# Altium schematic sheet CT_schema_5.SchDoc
size 242 x 245 mm
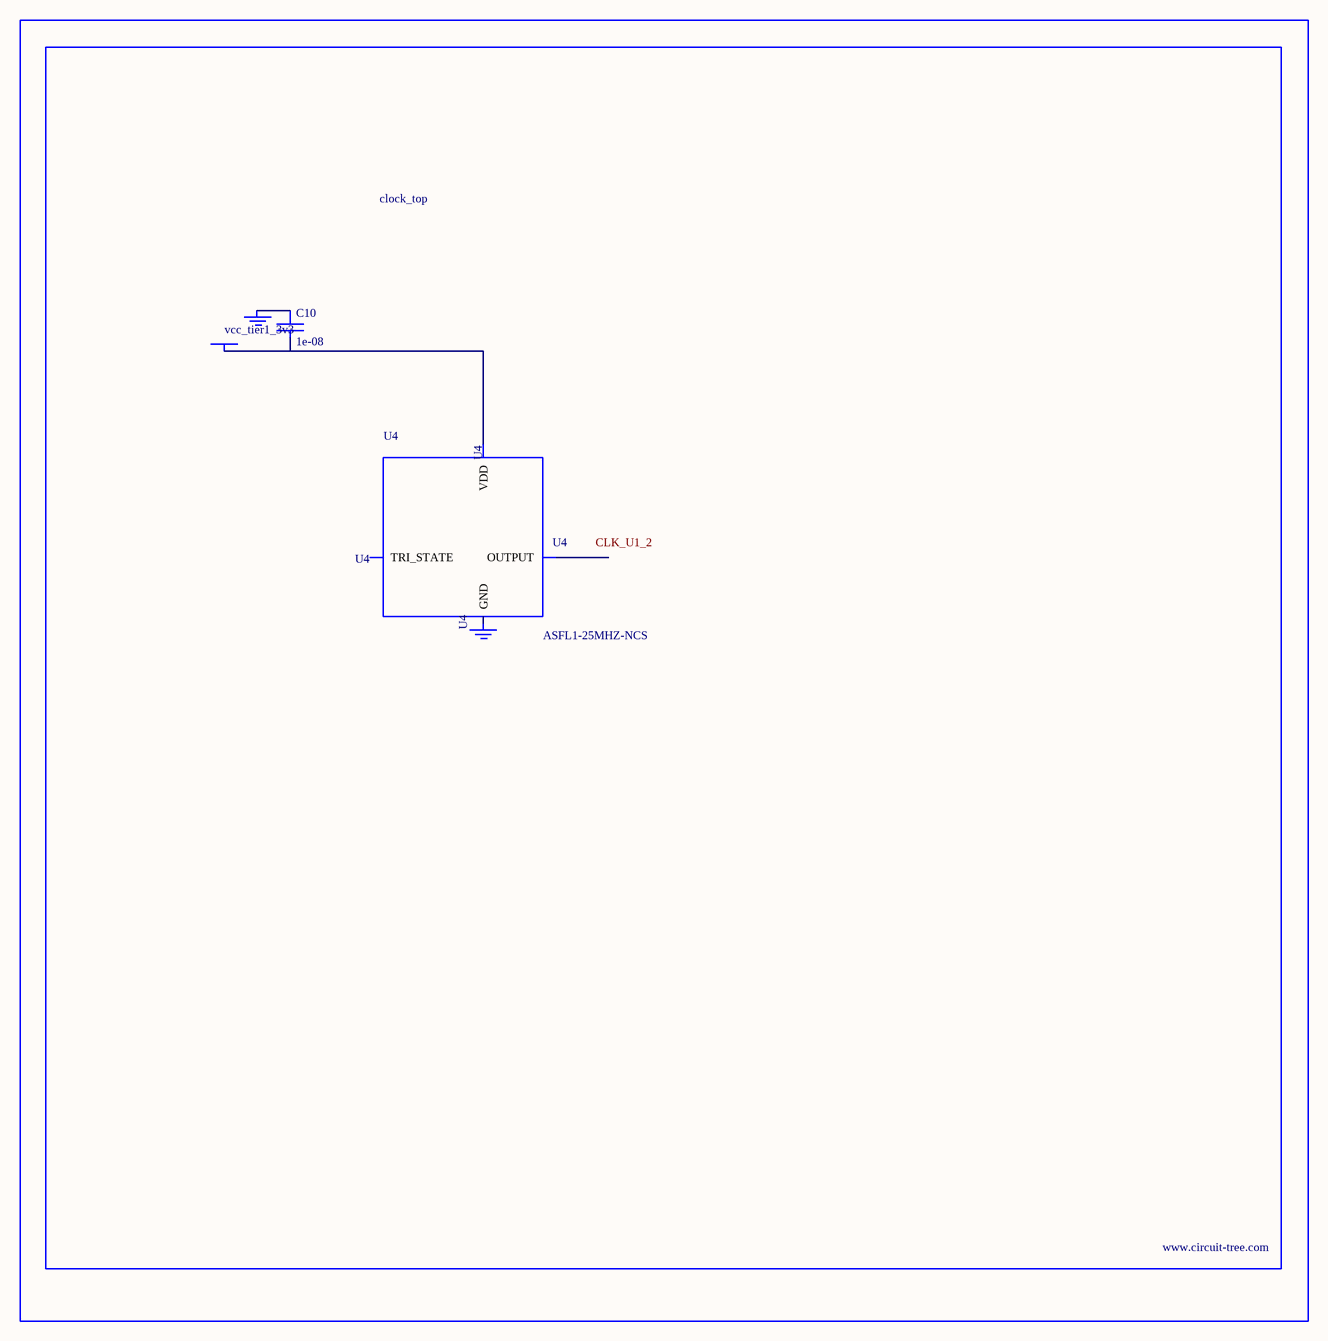
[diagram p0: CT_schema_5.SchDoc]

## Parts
BORDER4  (no value)
C10  1e-08  [C0402]
GND_INSTANCE_4_0  (no value)
GND_INSTANCE_4_1  (no value)
POWER_INSTANCE_4_0  vcc_tier1_3v3
U4  ASFL1-25MHZ-NCS  [ASFL1]

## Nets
NetC10_1: C10.1 GND_INSTANCE_4_0.0(GND)
NetC10_2: C10.2 POWER_INSTANCE_4_0.0(PWR) U4.4(VDD)

Not connected (* = marked no-connect by the designer): GND_INSTANCE_4_1 0(GND); U4 1(TRI_STATE) 2(GND) 3(OUTPUT)

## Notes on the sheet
- Labels drawn without touching a wire or pin: CLK_U1_2

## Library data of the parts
BORDER4 = BORDER_PAGE4
C10 = C0402C103K3RAC
GND_INSTANCE_4_0 GND_INSTANCE_4_1 = GND
POWER_INSTANCE_4_0 = PWR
